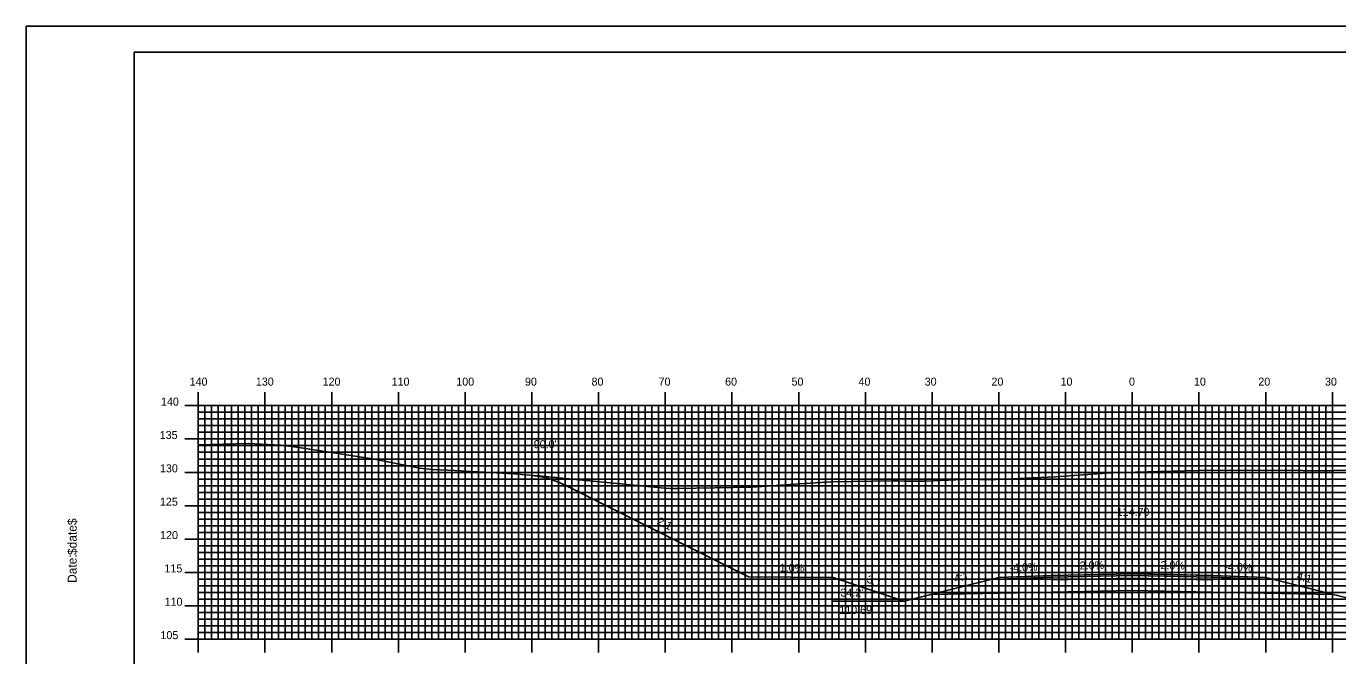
# Model space of a CAD drawing. Extents: x 1767300 to 1767643, y 442591 to 442811.
# Drawn here: x 1767300.1 to 1767496.7, y 442716.2 to 442810.5 of the extents above; entities that cross this region are included whole.
import ezdxf

# ---------------------------------------------------------------- set-up
doc = ezdxf.new("R2010")
doc.units = 0
for name, color, linetype in [('ANNOTATION', 7, 'Continuous'), ('BORDER', 7, 'Continuous'), ('D_Roadway_Centerline', 7, 'Continuous'), ('D_Roadway_Centerline_Text', 7, 'Continuous'), ('D_Roadway_Edge_Shoulder', 7, 'Continuous'), ('D_Roadway_Edge_TW', 7, 'Continuous'), ('D_Roadway_Pavement', 7, 'Continuous'), ('D_Roadway_SlopeLines', 7, 'Continuous'), ('D_Roadway_SubGrade', 7, 'Continuous'), ('D_Text_Standard', 7, 'Continuous'), ('H_V ANNOTATION', 7, 'Continuous'), ('MAJOR', 7, 'Continuous'), ('MINOR', 7, 'Continuous'), ('PDRAIN', 7, 'Continuous'), ('PLOT BOUNDARY', 7, 'Continuous'), ('S_Roadway_Centerline', 7, 'Continuous')]:
    doc.layers.add(name, color=color, linetype=linetype)

msp = doc.modelspace()

# ---------------------------------------------------------------- linework, layer by layer
at = {"layer": 'BORDER'}
msp.add_lwpolyline([(1767316.34, 442596.67), (1767636.34, 442596.67), (1767636.34, 442806.67), (1767316.34, 442806.67)], close=True, dxfattribs=at)
at = {"layer": 'D_Roadway_Centerline'}
msp.add_lwpolyline([(1767375.94, 442743.22), (1767377.19, 442743.05), (1767377.67, 442742.93), (1767378.44, 442742.75), (1767379.69, 442742.32), (1767380.94, 442741.76), (1767408.4, 442728.03), (1767408.4, 442728.02), (1767421.13, 442727.9), (1767431.76, 442724.35), (1767431.76, 442724.35), (1767435.76, 442725.35), (1767435.77, 442725.35), (1767445.94, 442727.9), (1767453.94, 442728.22), (1767453.94, 442728.22), (1767465.94, 442728.46), (1767465.94, 442728.46), (1767471.75, 442728.34), (1767477.93, 442728.22), (1767477.94, 442728.22), (1767485.93, 442727.9), (1767485.94, 442727.9), (1767490.78, 442726.69), (1767496.11, 442725.35), (1767496.11, 442725.35), (1767500.11, 442724.35)], dxfattribs=at)
at = {"layer": 'D_Roadway_Edge_Shoulder'}
for points in [[(1767453.94, 442728.22), (1767445.94, 442727.9), (1767445.94, 442727.65), (1767453.94, 442727.97)], [(1767477.94, 442728.22), (1767485.94, 442727.9), (1767485.94, 442727.65), (1767477.94, 442727.97)]]:
    msp.add_lwpolyline(points, close=True, dxfattribs=at)
at = {"layer": 'D_Roadway_Edge_TW'}
msp.add_lwpolyline([(1767453.94, 442727.97), (1767453.94, 442728.22), (1767465.94, 442728.46), (1767477.94, 442728.22), (1767477.94, 442727.97), (1767465.94, 442728.21)], close=True, dxfattribs=at)
at = {"layer": 'D_Roadway_Pavement'}
msp.add_lwpolyline([(1767453.94, 442727.55), (1767453.94, 442727.97), (1767465.94, 442728.21), (1767477.94, 442727.97), (1767477.94, 442727.55), (1767465.94, 442727.79)], close=True, dxfattribs=at)
at = {"layer": 'D_Roadway_SlopeLines'}
for points in [[(1767421.13, 442727.9), (1767408.4, 442728.02), (1767380.94, 442741.76), (1767379.69, 442742.32), (1767378.44, 442742.75), (1767377.19, 442743.05), (1767375.94, 442743.22)], [(1767431.76, 442724.35), (1767421.13, 442727.9)], [(1767445.94, 442727.9), (1767431.76, 442724.35)], [(1767485.94, 442727.9), (1767500.11, 442724.35)]]:
    msp.add_lwpolyline(points, dxfattribs=at)
at = {"layer": 'D_Roadway_SubGrade'}
msp.add_lwpolyline([(1767453.94, 442725.72), (1767435.76, 442725.35), (1767445.94, 442727.9), (1767445.94, 442727.65), (1767453.94, 442727.97), (1767465.94, 442728.21), (1767477.94, 442727.97), (1767485.94, 442727.65), (1767485.94, 442727.9), (1767496.11, 442725.35), (1767477.94, 442725.72), (1767465.94, 442725.96)], close=True, dxfattribs=at)
at = {"layer": 'MAJOR'}
for p, q in [((1767325.94, 442755.67), (1767325.94, 442753.67)), ((1767335.94, 442755.67), (1767335.94, 442753.67)), ((1767345.94, 442755.67), (1767345.94, 442753.67)), ((1767355.94, 442755.67), (1767355.94, 442753.67)), ((1767365.94, 442755.67), (1767365.94, 442753.67)), ((1767375.94, 442755.67), (1767375.94, 442753.67)), ((1767385.94, 442755.67), (1767385.94, 442753.67)), ((1767395.94, 442755.67), (1767395.94, 442753.67)), ((1767405.94, 442755.67), (1767405.94, 442753.67)), ((1767415.94, 442755.67), (1767415.94, 442753.67)), ((1767425.94, 442755.67), (1767425.94, 442753.67)), ((1767435.94, 442755.67), (1767435.94, 442753.67)), ((1767445.94, 442755.67), (1767445.94, 442753.67)), ((1767455.94, 442755.67), (1767455.94, 442753.67)), ((1767465.94, 442755.67), (1767465.94, 442753.67)), ((1767475.94, 442755.67), (1767475.94, 442753.67)), ((1767485.94, 442755.67), (1767485.94, 442753.67)), ((1767495.94, 442755.67), (1767495.94, 442753.67)), ((1767323.93, 442753.67), (1767325.94, 442753.67)), ((1767325.94, 442753.67), (1767605.94, 442753.67)), ((1767325.94, 442718.67), (1767325.94, 442753.67)), ((1767325.94, 442718.67), (1767325.94, 442753.67)), ((1767325.94, 442753.67), (1767605.94, 442753.67)), ((1767335.94, 442718.67), (1767335.94, 442753.67)), ((1767345.94, 442718.67), (1767345.94, 442753.67)), ((1767355.94, 442718.67), (1767355.94, 442753.67)), ((1767365.94, 442718.67), (1767365.94, 442753.67)), ((1767375.94, 442718.67), (1767375.94, 442753.67)), ((1767385.94, 442718.67), (1767385.94, 442753.67)), ((1767395.94, 442718.67), (1767395.94, 442753.67)), ((1767405.94, 442718.67), (1767405.94, 442753.67)), ((1767415.94, 442718.67), (1767415.94, 442753.67)), ((1767425.94, 442718.67), (1767425.94, 442753.67)), ((1767435.94, 442718.67), (1767435.94, 442753.67)), ((1767445.94, 442718.67), (1767445.94, 442753.67)), ((1767455.94, 442718.67), (1767455.94, 442753.67)), ((1767465.94, 442718.67), (1767465.94, 442753.67)), ((1767475.94, 442718.67), (1767475.94, 442753.67)), ((1767485.94, 442718.67), (1767485.94, 442753.67)), ((1767495.94, 442718.67), (1767495.94, 442753.67)), ((1767323.93, 442748.67), (1767325.94, 442748.67)), ((1767325.94, 442748.67), (1767605.94, 442748.67)), ((1767323.93, 442743.67), (1767325.94, 442743.67)), ((1767325.94, 442743.67), (1767605.94, 442743.67)), ((1767323.93, 442738.67), (1767325.94, 442738.67)), ((1767325.94, 442738.67), (1767605.94, 442738.67)), ((1767323.93, 442733.67), (1767325.94, 442733.67)), ((1767325.94, 442733.67), (1767605.94, 442733.67)), ((1767323.93, 442728.67), (1767325.94, 442728.67)), ((1767325.94, 442728.67), (1767605.94, 442728.67)), ((1767323.93, 442723.67), (1767325.94, 442723.67)), ((1767325.94, 442723.67), (1767605.94, 442723.67)), ((1767323.93, 442718.67), (1767325.94, 442718.67)), ((1767325.94, 442718.67), (1767605.94, 442718.67)), ((1767325.94, 442718.67), (1767605.94, 442718.67)), ((1767325.94, 442716.66), (1767325.94, 442718.67)), ((1767335.94, 442716.66), (1767335.94, 442718.67)), ((1767345.94, 442716.66), (1767345.94, 442718.67)), ((1767355.94, 442716.66), (1767355.94, 442718.67)), ((1767365.94, 442716.66), (1767365.94, 442718.67)), ((1767375.94, 442716.66), (1767375.94, 442718.67)), ((1767385.94, 442716.66), (1767385.94, 442718.67)), ((1767395.94, 442716.66), (1767395.94, 442718.67)), ((1767405.94, 442716.66), (1767405.94, 442718.67)), ((1767415.94, 442716.66), (1767415.94, 442718.67)), ((1767425.94, 442716.66), (1767425.94, 442718.67)), ((1767435.94, 442716.66), (1767435.94, 442718.67)), ((1767445.94, 442716.66), (1767445.94, 442718.67)), ((1767455.94, 442716.66), (1767455.94, 442718.67)), ((1767465.94, 442716.66), (1767465.94, 442718.67)), ((1767475.94, 442716.66), (1767475.94, 442718.67)), ((1767485.94, 442716.66), (1767485.94, 442718.67)), ((1767495.94, 442716.66), (1767495.94, 442718.67))]:
    msp.add_line(p, q, dxfattribs=at)
at = {"layer": 'MINOR'}
for p, q in [((1767326.94, 442718.67), (1767326.94, 442753.67)), ((1767327.94, 442718.67), (1767327.94, 442753.67)), ((1767328.94, 442718.67), (1767328.94, 442753.67)), ((1767329.94, 442718.67), (1767329.94, 442753.67)), ((1767330.94, 442718.67), (1767330.94, 442753.67)), ((1767331.94, 442718.67), (1767331.94, 442753.67)), ((1767332.94, 442718.67), (1767332.94, 442753.67)), ((1767333.94, 442718.67), (1767333.94, 442753.67)), ((1767334.94, 442718.67), (1767334.94, 442753.67)), ((1767336.94, 442718.67), (1767336.94, 442753.67)), ((1767337.94, 442718.67), (1767337.94, 442753.67)), ((1767338.94, 442718.67), (1767338.94, 442753.67)), ((1767339.94, 442718.67), (1767339.94, 442753.67)), ((1767340.94, 442718.67), (1767340.94, 442753.67)), ((1767341.94, 442718.67), (1767341.94, 442753.67)), ((1767342.94, 442718.67), (1767342.94, 442753.67)), ((1767343.94, 442718.67), (1767343.94, 442753.67)), ((1767344.94, 442718.67), (1767344.94, 442753.67)), ((1767346.94, 442718.67), (1767346.94, 442753.67)), ((1767347.94, 442718.67), (1767347.94, 442753.67)), ((1767348.94, 442718.67), (1767348.94, 442753.67)), ((1767349.94, 442718.67), (1767349.94, 442753.67)), ((1767350.94, 442718.67), (1767350.94, 442753.67)), ((1767351.94, 442718.67), (1767351.94, 442753.67)), ((1767352.94, 442718.67), (1767352.94, 442753.67)), ((1767353.94, 442718.67), (1767353.94, 442753.67)), ((1767354.94, 442718.67), (1767354.94, 442753.67)), ((1767356.94, 442718.67), (1767356.94, 442753.67)), ((1767357.94, 442718.67), (1767357.94, 442753.67)), ((1767358.94, 442718.67), (1767358.94, 442753.67)), ((1767359.94, 442718.67), (1767359.94, 442753.67)), ((1767360.94, 442718.67), (1767360.94, 442753.67)), ((1767361.94, 442718.67), (1767361.94, 442753.67)), ((1767362.94, 442718.67), (1767362.94, 442753.67)), ((1767363.94, 442718.67), (1767363.94, 442753.67)), ((1767364.94, 442718.67), (1767364.94, 442753.67)), ((1767366.94, 442718.67), (1767366.94, 442753.67)), ((1767367.94, 442718.67), (1767367.94, 442753.67)), ((1767368.94, 442718.67), (1767368.94, 442753.67)), ((1767369.94, 442718.67), (1767369.94, 442753.67)), ((1767370.94, 442718.67), (1767370.94, 442753.67)), ((1767371.94, 442718.67), (1767371.94, 442753.67)), ((1767372.94, 442718.67), (1767372.94, 442753.67)), ((1767373.94, 442718.67), (1767373.94, 442753.67)), ((1767374.94, 442718.67), (1767374.94, 442753.67)), ((1767376.94, 442718.67), (1767376.94, 442753.67)), ((1767377.94, 442718.67), (1767377.94, 442753.67)), ((1767378.94, 442718.67), (1767378.94, 442753.67)), ((1767379.94, 442718.67), (1767379.94, 442753.67)), ((1767380.94, 442718.67), (1767380.94, 442753.67)), ((1767381.94, 442718.67), (1767381.94, 442753.67)), ((1767382.94, 442718.67), (1767382.94, 442753.67)), ((1767383.94, 442718.67), (1767383.94, 442753.67)), ((1767384.94, 442718.67), (1767384.94, 442753.67)), ((1767386.94, 442718.67), (1767386.94, 442753.67)), ((1767387.94, 442718.67), (1767387.94, 442753.67)), ((1767388.94, 442718.67), (1767388.94, 442753.67)), ((1767389.94, 442718.67), (1767389.94, 442753.67)), ((1767390.94, 442718.67), (1767390.94, 442753.67)), ((1767391.94, 442718.67), (1767391.94, 442753.67)), ((1767392.94, 442718.67), (1767392.94, 442753.67)), ((1767393.94, 442718.67), (1767393.94, 442753.67)), ((1767394.94, 442718.67), (1767394.94, 442753.67)), ((1767396.94, 442718.67), (1767396.94, 442753.67)), ((1767397.94, 442718.67), (1767397.94, 442753.67)), ((1767398.94, 442718.67), (1767398.94, 442753.67)), ((1767399.94, 442718.67), (1767399.94, 442753.67)), ((1767400.94, 442718.67), (1767400.94, 442753.67)), ((1767401.94, 442718.67), (1767401.94, 442753.67)), ((1767402.94, 442718.67), (1767402.94, 442753.67)), ((1767403.94, 442718.67), (1767403.94, 442753.67)), ((1767404.94, 442718.67), (1767404.94, 442753.67)), ((1767406.94, 442718.67), (1767406.94, 442753.67)), ((1767407.94, 442718.67), (1767407.94, 442753.67)), ((1767408.94, 442718.67), (1767408.94, 442753.67)), ((1767409.94, 442718.67), (1767409.94, 442753.67)), ((1767410.94, 442718.67), (1767410.94, 442753.67)), ((1767411.94, 442718.67), (1767411.94, 442753.67)), ((1767412.94, 442718.67), (1767412.94, 442753.67)), ((1767413.94, 442718.67), (1767413.94, 442753.67)), ((1767414.94, 442718.67), (1767414.94, 442753.67)), ((1767416.94, 442718.67), (1767416.94, 442753.67)), ((1767417.94, 442718.67), (1767417.94, 442753.67)), ((1767418.94, 442718.67), (1767418.94, 442753.67)), ((1767419.94, 442718.67), (1767419.94, 442753.67)), ((1767420.94, 442718.67), (1767420.94, 442753.67)), ((1767421.94, 442718.67), (1767421.94, 442753.67)), ((1767422.94, 442718.67), (1767422.94, 442753.67)), ((1767423.94, 442718.67), (1767423.94, 442753.67)), ((1767424.94, 442718.67), (1767424.94, 442753.67)), ((1767426.94, 442718.67), (1767426.94, 442753.67)), ((1767427.94, 442718.67), (1767427.94, 442753.67)), ((1767428.94, 442718.67), (1767428.94, 442753.67)), ((1767429.94, 442718.67), (1767429.94, 442753.67)), ((1767430.94, 442718.67), (1767430.94, 442753.67)), ((1767431.94, 442718.67), (1767431.94, 442753.67)), ((1767432.94, 442718.67), (1767432.94, 442753.67)), ((1767433.94, 442718.67), (1767433.94, 442753.67)), ((1767434.94, 442718.67), (1767434.94, 442753.67)), ((1767436.94, 442718.67), (1767436.94, 442753.67)), ((1767437.94, 442718.67), (1767437.94, 442753.67)), ((1767438.94, 442718.67), (1767438.94, 442753.67)), ((1767439.94, 442718.67), (1767439.94, 442753.67)), ((1767440.94, 442718.67), (1767440.94, 442753.67)), ((1767441.94, 442718.67), (1767441.94, 442753.67)), ((1767442.94, 442718.67), (1767442.94, 442753.67)), ((1767443.94, 442718.67), (1767443.94, 442753.67)), ((1767444.94, 442718.67), (1767444.94, 442753.67)), ((1767446.94, 442718.67), (1767446.94, 442753.67)), ((1767447.94, 442718.67), (1767447.94, 442753.67)), ((1767448.94, 442718.67), (1767448.94, 442753.67)), ((1767449.94, 442718.67), (1767449.94, 442753.67)), ((1767450.94, 442718.67), (1767450.94, 442753.67)), ((1767451.94, 442718.67), (1767451.94, 442753.67)), ((1767452.94, 442718.67), (1767452.94, 442753.67)), ((1767453.94, 442718.67), (1767453.94, 442753.67)), ((1767454.94, 442718.67), (1767454.94, 442753.67)), ((1767456.94, 442718.67), (1767456.94, 442753.67)), ((1767457.94, 442718.67), (1767457.94, 442753.67)), ((1767458.94, 442718.67), (1767458.94, 442753.67)), ((1767459.94, 442718.67), (1767459.94, 442753.67)), ((1767460.94, 442718.67), (1767460.94, 442753.67)), ((1767461.94, 442718.67), (1767461.94, 442753.67)), ((1767462.94, 442718.67), (1767462.94, 442753.67)), ((1767463.94, 442718.67), (1767463.94, 442753.67)), ((1767464.94, 442718.67), (1767464.94, 442753.67)), ((1767466.94, 442718.67), (1767466.94, 442753.67)), ((1767467.94, 442718.67), (1767467.94, 442753.67)), ((1767468.94, 442718.67), (1767468.94, 442753.67)), ((1767469.94, 442718.67), (1767469.94, 442753.67)), ((1767470.94, 442718.67), (1767470.94, 442753.67)), ((1767471.94, 442718.67), (1767471.94, 442753.67)), ((1767472.94, 442718.67), (1767472.94, 442753.67)), ((1767473.94, 442718.67), (1767473.94, 442753.67)), ((1767474.94, 442718.67), (1767474.94, 442753.67)), ((1767476.94, 442718.67), (1767476.94, 442753.67)), ((1767477.94, 442718.67), (1767477.94, 442753.67)), ((1767478.94, 442718.67), (1767478.94, 442753.67)), ((1767479.94, 442718.67), (1767479.94, 442753.67)), ((1767480.94, 442718.67), (1767480.94, 442753.67)), ((1767481.94, 442718.67), (1767481.94, 442753.67)), ((1767482.94, 442718.67), (1767482.94, 442753.67)), ((1767483.94, 442718.67), (1767483.94, 442753.67)), ((1767484.94, 442718.67), (1767484.94, 442753.67)), ((1767486.94, 442718.67), (1767486.94, 442753.67)), ((1767487.94, 442718.67), (1767487.94, 442753.67)), ((1767488.94, 442718.67), (1767488.94, 442753.67)), ((1767489.94, 442718.67), (1767489.94, 442753.67)), ((1767490.94, 442718.67), (1767490.94, 442753.67)), ((1767491.94, 442718.67), (1767491.94, 442753.67)), ((1767492.94, 442718.67), (1767492.94, 442753.67)), ((1767493.94, 442718.67), (1767493.94, 442753.67)), ((1767494.94, 442718.67), (1767494.94, 442753.67)), ((1767325.94, 442752.67), (1767605.94, 442752.67)), ((1767325.94, 442752.67), (1767327.94, 442752.67)), ((1767325.94, 442751.67), (1767605.94, 442751.67)), ((1767325.94, 442751.67), (1767327.94, 442751.67)), ((1767325.94, 442750.67), (1767605.94, 442750.67)), ((1767325.94, 442750.67), (1767327.94, 442750.67)), ((1767325.94, 442749.67), (1767605.94, 442749.67)), ((1767325.94, 442749.67), (1767327.94, 442749.67)), ((1767325.94, 442747.67), (1767605.94, 442747.67)), ((1767325.94, 442747.67), (1767327.94, 442747.67)), ((1767325.94, 442746.67), (1767605.94, 442746.67)), ((1767325.94, 442746.67), (1767327.94, 442746.67)), ((1767325.94, 442745.67), (1767605.94, 442745.67)), ((1767325.94, 442745.67), (1767327.94, 442745.67)), ((1767325.94, 442744.67), (1767605.94, 442744.67)), ((1767325.94, 442744.67), (1767327.94, 442744.67)), ((1767325.94, 442742.67), (1767605.94, 442742.67)), ((1767325.94, 442742.67), (1767327.94, 442742.67)), ((1767325.94, 442741.67), (1767605.94, 442741.67)), ((1767325.94, 442741.67), (1767327.94, 442741.67)), ((1767325.94, 442740.67), (1767605.94, 442740.67)), ((1767325.94, 442740.67), (1767327.94, 442740.67)), ((1767325.94, 442739.67), (1767605.94, 442739.67)), ((1767325.94, 442739.67), (1767327.94, 442739.67)), ((1767325.94, 442737.67), (1767605.94, 442737.67)), ((1767325.94, 442737.67), (1767327.94, 442737.67)), ((1767325.94, 442736.67), (1767605.94, 442736.67)), ((1767325.94, 442736.67), (1767327.94, 442736.67)), ((1767325.94, 442735.67), (1767605.94, 442735.67)), ((1767325.94, 442735.67), (1767327.94, 442735.67)), ((1767325.94, 442734.67), (1767605.94, 442734.67)), ((1767325.94, 442734.67), (1767327.94, 442734.67)), ((1767325.94, 442732.67), (1767605.94, 442732.67)), ((1767325.94, 442732.67), (1767327.94, 442732.67)), ((1767325.94, 442731.67), (1767605.94, 442731.67)), ((1767325.94, 442731.67), (1767327.94, 442731.67)), ((1767325.94, 442730.67), (1767605.94, 442730.67)), ((1767325.94, 442730.67), (1767327.94, 442730.67)), ((1767325.94, 442729.67), (1767605.94, 442729.67)), ((1767325.94, 442729.67), (1767327.94, 442729.67)), ((1767325.94, 442727.67), (1767605.94, 442727.67)), ((1767325.94, 442727.67), (1767327.94, 442727.67)), ((1767325.94, 442726.67), (1767605.94, 442726.67)), ((1767325.94, 442726.67), (1767327.94, 442726.67)), ((1767325.94, 442725.67), (1767605.94, 442725.67)), ((1767325.94, 442725.67), (1767327.94, 442725.67)), ((1767325.94, 442724.67), (1767605.94, 442724.67)), ((1767325.94, 442724.67), (1767327.94, 442724.67)), ((1767325.94, 442722.67), (1767605.94, 442722.67)), ((1767325.94, 442722.67), (1767327.94, 442722.67)), ((1767325.94, 442721.67), (1767605.94, 442721.67)), ((1767325.94, 442721.67), (1767327.94, 442721.67)), ((1767325.94, 442720.67), (1767605.94, 442720.67)), ((1767325.94, 442720.67), (1767327.94, 442720.67)), ((1767325.94, 442719.67), (1767605.94, 442719.67)), ((1767325.94, 442719.67), (1767327.94, 442719.67))]:
    msp.add_line(p, q, dxfattribs=at)
at = {"layer": 'PDRAIN'}
msp.add_line((1767421.04, 442724.35), (1767431.76, 442724.35), dxfattribs=at)
at = {"layer": 'PLOT BOUNDARY'}
msp.add_lwpolyline([(1767300.15, 442590.55), (1767640.15, 442590.55), (1767640.15, 442810.55), (1767300.15, 442810.55)], close=True, dxfattribs=at)
at = {"layer": 'S_Roadway_Centerline'}
msp.add_lwpolyline([(1767325.94, 442747.78), (1767333.4, 442748), (1767338.3, 442747.75), (1767341.08, 442747.39), (1767352.34, 442745.65), (1767359.13, 442744.29), (1767361.03, 442744.1), (1767364.39, 442743.97), (1767373.26, 442743.45), (1767378, 442743.05), (1767395.31, 442741.37), (1767396.67, 442741.25), (1767397.71, 442741.26), (1767408.98, 442741.47), (1767416.11, 442741.97), (1767420.83, 442742.26), (1767430.11, 442742.39), (1767430.73, 442742.4), (1767431.75, 442742.34), (1767435.04, 442742.34), (1767441.65, 442742.63), (1767444.45, 442742.55), (1767454.42, 442742.98), (1767462.77, 442743.59), (1767473.72, 442743.91), (1767478.14, 442744.01), (1767491.49, 442743.93), (1767493.37, 442743.92), (1767504.53, 442744.11)], dxfattribs=at)

# ---------------------------------------------------------------- texts
at = {"layer": 'ANNOTATION'}
for s, rotation, p in [('2:1', 333.4362, (1767394.6, 442735.96)), ('1.0%', 359.4283, (1767413.1, 442728.78)), ('-4.0%', 2.2905, (1767447.57, 442728.76)), ('-2.0%', 1.1458, (1767457.54, 442729.09)), ('-2.0%', 358.8542, (1767469.62, 442729.18)), ('-4.0%', 357.7095, (1767479.73, 442728.95)), ('3:1', 341.563, (1767426.05, 442727.17)), ('4:1', 14.0395, (1767439.39, 442727.12)), ('4:1', 345.9612, (1767490.53, 442727.61))]:
    msp.add_text(s, height=1.2, rotation=rotation, dxfattribs=at).set_placement(p)
for s, p in [("34.2'", (1767422.2, 442725.04)), ('110.69', (1767422.03, 442722.44))]:
    msp.add_text(s, height=1.2, dxfattribs=at).set_placement(p)
at = {"layer": 'BORDER'}
for s, p in [('$date$', (1767307.71, 442731.28)), ('Date:', (1767307.71, 442727.1))]:
    msp.add_text(s, height=1.339, rotation=90, dxfattribs=at).set_placement(p)
at = {"layer": 'D_Roadway_Centerline'}
for s, p in [('C', (1767465.93, 442728.46)), ('L', (1767465.94, 442728.45))]:
    msp.add_text(s, height=0.0146, dxfattribs=at).set_placement(p)
at = {"layer": 'D_Roadway_Centerline_Text'}
msp.add_text('114.79', height=1.2, dxfattribs=at).set_placement((1767463.61, 442737.14))
at = {"layer": 'D_Text_Standard'}
msp.add_text("90.0'", height=1.2, dxfattribs=at).set_placement((1767376.22, 442747.29))
at = {"layer": 'H_V ANNOTATION'}
for s, p in [('140', (1767324.64, 442756.67)), ('130', (1767334.57, 442756.67)), ('120', (1767344.58, 442756.67)), ('110', (1767354.92, 442756.67)), ('100', (1767364.62, 442756.67)), ('90', (1767374.91, 442756.67)), ('80', (1767384.89, 442756.67)), ('70', (1767394.94, 442756.67)), ('60', (1767404.91, 442756.67)), ('50', (1767414.87, 442756.67)), ('40', (1767424.91, 442756.67)), ('30', (1767434.83, 442756.67)), ('20', (1767444.84, 442756.67)), ('10', (1767455.19, 442756.67)), ('0', (1767465.45, 442756.67)), ('10', (1767475.19, 442756.67)), ('20', (1767484.84, 442756.67)), ('30', (1767494.83, 442756.67)), ('140', (1767320.35, 442753.67)), ('135', (1767320.16, 442748.67)), ('130', (1767320.2, 442743.67)), ('125', (1767320.19, 442738.67)), ('120', (1767320.22, 442733.67)), ('115', (1767320.87, 442728.67)), ('110', (1767320.9, 442723.67)), ('105', (1767320.27, 442718.67))]:
    msp.add_text(s, height=1.2, dxfattribs=at).set_placement(p)
at = {"layer": 'MAJOR'}
msp.add_text('-', height=0.012, dxfattribs=at).set_placement((1767325.93, 442718.67))

doc.saveas('drawing.dxf')
